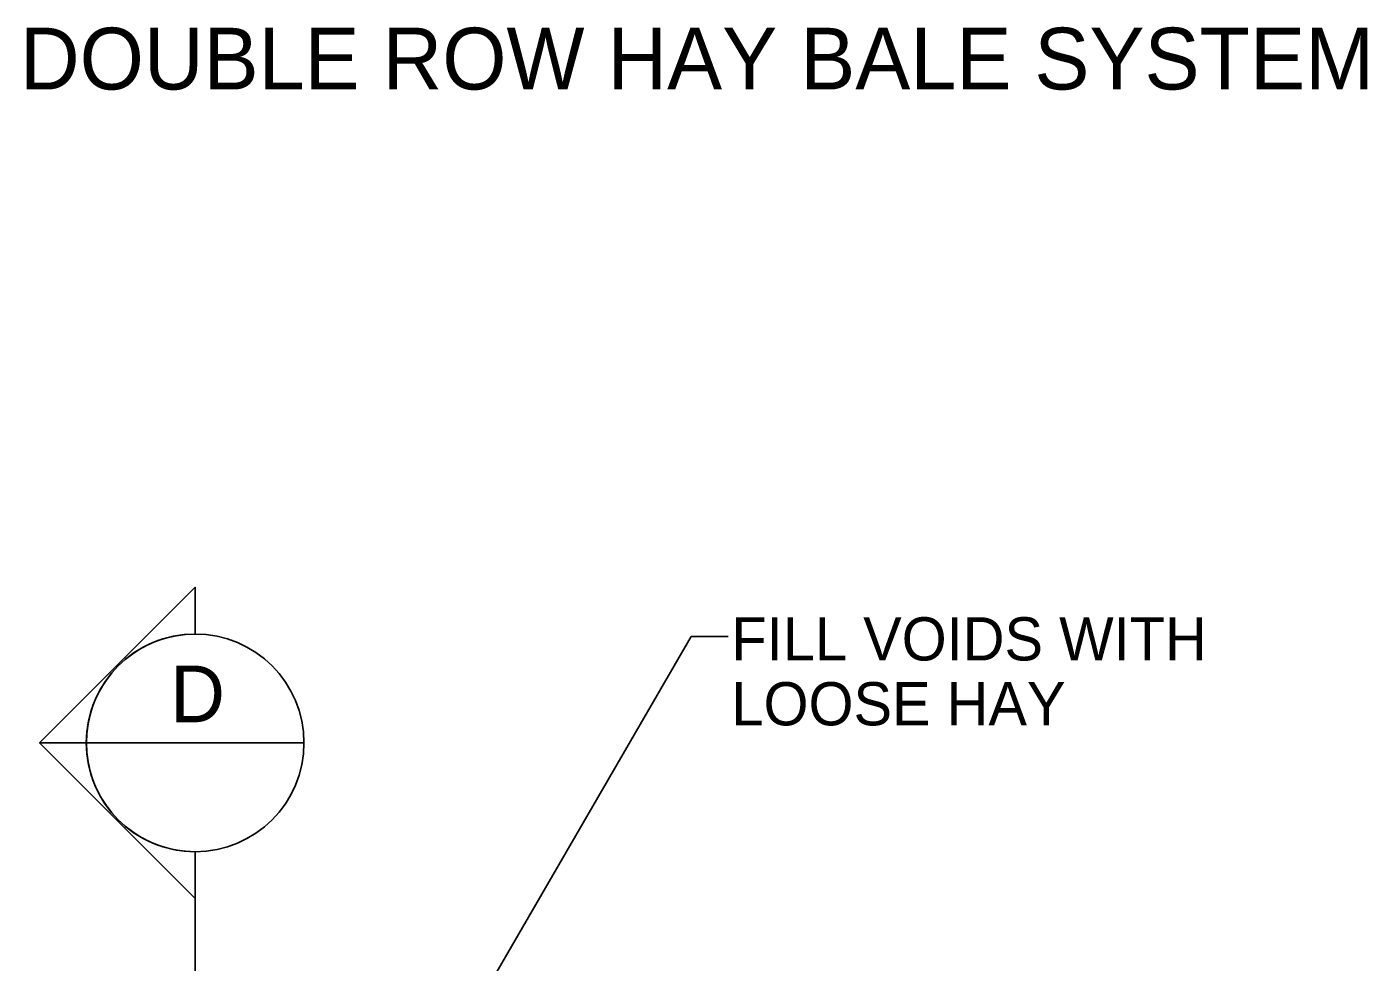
# Model space of a CAD drawing. Extents: x 0 to 2.83, y -0.06 to 1.83.
# Drawn here: x 2.0031 to 2.2744, y 1.1062 to 1.2955 of the extents above; entities that cross this region are included whole.
import ezdxf

# ---------------------------------------------------------------- set-up
doc = ezdxf.new("R2010")
doc.units = 0
for name, color, linetype in [('Edge_of_Truck_Apron', 7, 'Continuous'), ('Longitudinal Joint', 7, 'Continuous'), ('sb_Detail Title Text', 7, 'Continuous')]:
    doc.layers.add(name, color=color, linetype=linetype)

msp = doc.modelspace()

# ---------------------------------------------------------------- linework, layer by layer
at = {"layer": 'Edge_of_Truck_Apron'}
for p, q in [((2.06595, 1.04864), (2.13753, 1.17213)), ((2.14504, 1.17213), (2.13753, 1.17213)), ((2.00569, 1.15061), (2.05919, 1.15061)), ((2.03704, 0.83266), (2.03717, 1.11913))]:
    msp.add_line(p, q, dxfattribs=at)
msp.add_lwpolyline([(2.03717, 1.17263), (2.03525, 1.17254), (2.03335, 1.17229), (2.03147, 1.17188), (2.02964, 1.1713), (2.02787, 1.17056), (2.02616, 1.16968), (2.02454, 1.16864), (2.02302, 1.16748), (2.0216, 1.16618), (2.02031, 1.16476), (2.01914, 1.16324), (2.0181, 1.16162), (2.01722, 1.15991), (2.01648, 1.15814), (2.01591, 1.15631), (2.01549, 1.15443), (2.01524, 1.15253), (2.01516, 1.15061), (2.01524, 1.14869), (2.01549, 1.14679), (2.01591, 1.14491), (2.01648, 1.14308), (2.01722, 1.14131), (2.0181, 1.1396), (2.01914, 1.13798), (2.02031, 1.13646), (2.0216, 1.13504), (2.02302, 1.13375), (2.02454, 1.13258), (2.02616, 1.13154), (2.02787, 1.13066), (2.02964, 1.12992), (2.03147, 1.12934), (2.03335, 1.12893), (2.03525, 1.12868), (2.03717, 1.12859), (2.03717, 1.11913), (2.00569, 1.15061), (2.03717, 1.18209)], close=True, dxfattribs=at)
msp.add_circle((2.03717, 1.15061), 0.02202, dxfattribs=at)
at = {"layer": 'Longitudinal Joint'}
for p in [(2.06595, 1.04864), (2.14504, 1.17213)]:
    msp.add_line(p, (2.13753, 1.17213), dxfattribs=at)

# ---------------------------------------------------------------- texts
at = {"layer": 'Edge_of_Truck_Apron'}
for s, p in [('FILL VOIDS WITH', (2.1457, 1.16728)), ('LOOSE HAY', (2.1457, 1.15415))]:
    msp.add_text(s, height=0.00875, dxfattribs=at).set_placement(p)
at = {"layer": 'Longitudinal Joint'}
msp.add_text('DOUBLE ROW HAY BALE SYSTEM ', height=0.0125, rotation=360, dxfattribs=at).set_placement((2.00173, 1.28283))
at = {"layer": 'sb_Detail Title Text'}
msp.add_text('D', height=0.01147, dxfattribs=at).set_placement((2.03213, 1.15479))

doc.saveas('drawing.dxf')
